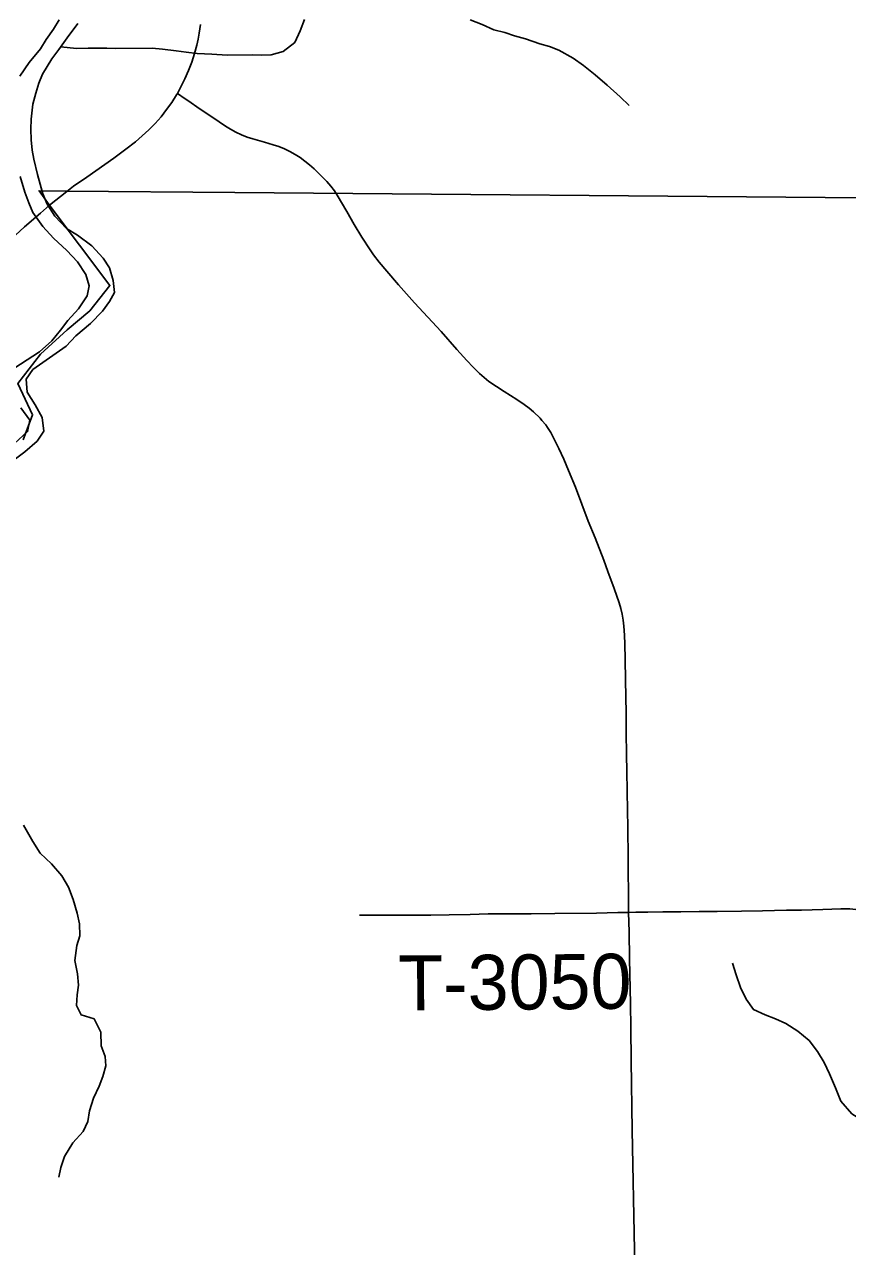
# Model space of a CAD drawing. Extents: x -7.5 to 53.5, y 0 to 22.
# Drawn here: x 3.721 to 4.57, y 15.27 to 16.532 of the extents above; entities that cross this region are included whole.
import ezdxf

# ---------------------------------------------------------------- set-up
doc = ezdxf.new("R2010")
doc.units = 0
for name, color, linetype in [('GM_X_Corporation', 7, 'Continuous'), ('GM_X_County_Road', 7, 'Continuous'), ('GM_X_Major_River', 7, 'Continuous'), ('GM_X_Minor_River', 7, 'Continuous'), ('GM_X_State_Route', 7, 'Continuous'), ('GM_X_Township_Road', 7, 'Continuous'), ('GM_X_Township_Road_Text', 7, 'Continuous')]:
    doc.layers.add(name, color=color, linetype=linetype)

msp = doc.modelspace()

# ---------------------------------------------------------------- linework, layer by layer
at = {"layer": 'GM_X_Corporation'}
msp.add_lwpolyline([(4.5873, 16.3533), (3.9378, 16.3588), (3.7641, 16.3602), (3.7357, 16.3606), (3.7462, 16.3461), (3.8088, 16.2627), (3.788, 16.2365), (3.7647, 16.2168), (3.737, 16.1919), (3.7138, 16.1615), (3.729, 16.1293), (3.7192, 16.1034)], dxfattribs=at)
at = {"layer": 'GM_X_County_Road'}
for points in [[(4.0432, 16.3561), (4.0404, 16.3605), (4.0367, 16.3654), (4.0326, 16.37), (4.0262, 16.3767), (4.0195, 16.3831), (4.0148, 16.3872), (4.01, 16.3911), (4.005, 16.3947), (3.9998, 16.398), (3.9944, 16.4011), (3.9889, 16.4037), (3.9831, 16.4061), (3.9773, 16.4081), (3.9683, 16.4107), (3.9563, 16.414), (3.9503, 16.416), (3.9445, 16.4183), (3.9388, 16.4209), (3.9333, 16.424), (3.9279, 16.4273), (3.9149, 16.436), (3.902, 16.4448), (3.8891, 16.4536), (3.8865, 16.4554), (3.8784, 16.4611)], [(4.344, 15.6154), (4.3438, 15.6342), (4.3436, 15.6591), (4.3435, 15.6716), (4.343, 15.7027), (4.3428, 15.7214), (4.3426, 15.74), (4.3422, 15.7618), (4.3419, 15.7773), (4.3416, 15.8022), (4.3415, 15.8209), (4.3409, 15.8551), (4.3405, 15.8769), (4.3402, 15.8924), (4.3398, 15.9017), (4.339, 15.911), (4.3382, 15.9171), (4.3372, 15.9232), (4.3358, 15.9292), (4.3341, 15.9351), (4.329, 15.9497), (4.3227, 15.9673), (4.3183, 15.979), (4.3093, 16.0022), (4.3024, 16.0195), (4.2957, 16.0369), (4.289, 16.0544), (4.2821, 16.0717), (4.2772, 16.0832), (4.2721, 16.0944), (4.2666, 16.1055), (4.2636, 16.1109), (4.2603, 16.1161), (4.2585, 16.1187), (4.2546, 16.1234), (4.2526, 16.1257), (4.2459, 16.1321), (4.2412, 16.1361), (4.2363, 16.1398), (4.2286, 16.145), (4.2154, 16.1532), (4.2075, 16.1583), (4.1998, 16.1637), (4.1949, 16.1676), (4.1902, 16.1718), (4.1835, 16.1784), (4.1772, 16.1852), (4.1668, 16.1967), (4.1504, 16.2153), (4.1232, 16.2449), (4.1067, 16.2634), (4.0945, 16.2774), (4.0865, 16.2869), (4.0808, 16.2943), (4.0772, 16.2994), (4.0688, 16.3125), (4.0609, 16.3258), (4.0532, 16.3392), (4.0432, 16.3561)], [(4.3617, 15.1179), (4.356, 15.1334), (4.3539, 15.1425), (4.3524, 15.1517), (4.3516, 15.161), (4.3512, 15.1766), (4.3511, 15.2169), (4.3502, 15.2665), (4.3475, 15.3906), (4.3465, 15.462), (4.3463, 15.4961), (4.346, 15.5209), (4.345, 15.5673), (4.3444, 15.5952), (4.344, 15.6154)]]:
    msp.add_lwpolyline(points, dxfattribs=at)
at = {"layer": 'GM_X_Major_River'}
for points in [[(3.7565, 16.5369), (3.7505, 16.5274), (3.743, 16.5167), (3.737, 16.5072), (3.7253, 16.4931), (3.7159, 16.4787)], [(3.7636, 16.1999), (3.7735, 16.2106), (3.7886, 16.2236), (3.801, 16.2361), (3.8085, 16.246), (3.8134, 16.2555), (3.8122, 16.268), (3.8084, 16.2809), (3.8019, 16.2908), (3.7901, 16.3036), (3.7753, 16.3146), (3.7639, 16.3214), (3.7521, 16.3342), (3.7441, 16.3467), (3.7395, 16.3573), (3.7368, 16.3672), (3.7341, 16.3774), (3.7302, 16.393), (3.7287, 16.4024), (3.7275, 16.4131), (3.7271, 16.4241), (3.7274, 16.4343), (3.7292, 16.4499), (3.7322, 16.4613), (3.7356, 16.4715), (3.7393, 16.481), (3.7487, 16.4966), (3.7559, 16.5065), (3.7646, 16.5183), (3.7755, 16.5332)], [(3.7163, 16.3751), (3.7209, 16.3592), (3.7251, 16.3482), (3.7293, 16.3379), (3.7396, 16.3236), (3.7507, 16.3115), (3.7644, 16.299), (3.7754, 16.2873), (3.7838, 16.274), (3.7873, 16.2623), (3.7854, 16.252), (3.7764, 16.2387), (3.7654, 16.2265), (3.7579, 16.2166), (3.7488, 16.2056), (3.736, 16.1941)], [(3.736, 16.1941), (3.7039, 16.1731)], [(3.7085, 16.0817), (3.7209, 16.0909), (3.7337, 16.102), (3.7405, 16.1123), (3.7388, 16.1264), (3.7315, 16.1396), (3.7234, 16.1524), (3.7222, 16.1661), (3.7293, 16.176), (3.7636, 16.1999)], [(3.7167, 16.1364), (3.7263, 16.1236), (3.7238, 16.1118), (3.7102, 16.0995)]]:
    msp.add_lwpolyline(points, dxfattribs=at)
at = {"layer": 'GM_X_Minor_River'}
for points in [[(3.7578, 16.5091), (3.7745, 16.5074), (3.7862, 16.5078), (3.8055, 16.5079), (3.815, 16.5075), (3.8522, 16.5077), (3.8632, 16.5069), (3.8772, 16.5051), (3.8874, 16.5036), (3.8988, 16.5021), (3.914, 16.5014), (3.9299, 16.5007), (3.9556, 16.5008), (3.9655, 16.5005), (3.9753, 16.5009), (3.9875, 16.5044), (3.9995, 16.5135), (4.0052, 16.5257), (4.0097, 16.5375)], [(4.1806, 16.537), (4.1927, 16.5321), (4.2049, 16.5268), (4.2163, 16.5238), (4.2261, 16.5205), (4.2375, 16.5175), (4.2523, 16.5122), (4.2622, 16.5096), (4.2721, 16.5058), (4.2869, 16.4975), (4.2975, 16.49), (4.3093, 16.4802), (4.3219, 16.4696), (4.3352, 16.4575), (4.3447, 16.4484)], [(3.7195, 15.7054), (3.7291, 15.6884), (3.7368, 15.6764), (3.7486, 15.6655), (3.759, 15.653), (3.7659, 15.6413), (3.771, 15.6285), (3.7749, 15.6145), (3.7773, 15.6035), (3.7778, 15.591), (3.7748, 15.5811), (3.7727, 15.5655), (3.7754, 15.5519), (3.7763, 15.5401), (3.7749, 15.5303), (3.7742, 15.5192), (3.7792, 15.5094), (3.7925, 15.5054), (3.7995, 15.4918), (3.7996, 15.4777), (3.8039, 15.4664), (3.8047, 15.4569), (3.8014, 15.4459), (3.7977, 15.436), (3.7918, 15.4234), (3.7877, 15.4105), (3.7859, 15.3995), (3.7811, 15.3892), (3.7706, 15.3773), (3.762, 15.3632), (3.7583, 15.3518), (3.7561, 15.3419)], [(4.5998, 15.3899), (4.5998, 15.3918), (4.5861, 15.4), (4.5742, 15.4075), (4.5631, 15.4203), (4.5573, 15.4343), (4.5511, 15.4486), (4.5457, 15.4603), (4.5388, 15.4717), (4.5303, 15.483), (4.5185, 15.4927), (4.5063, 15.5006), (4.4956, 15.5054), (4.485, 15.5095), (4.4728, 15.5151), (4.4651, 15.5256), (4.4593, 15.5377), (4.455, 15.5509), (4.4511, 15.563)]]:
    msp.add_lwpolyline(points, dxfattribs=at)
at = {"layer": 'GM_X_State_Route'}
msp.add_line((3.7464, 16.3455), (3.7643, 16.3596), dxfattribs=at)
for points in [[(3.7643, 16.3596), (3.7713, 16.3651), (3.7849, 16.3745), (3.8128, 16.3941), (3.8253, 16.4034), (3.835, 16.411), (3.8421, 16.4171), (3.8489, 16.4234), (3.8554, 16.4301), (3.8615, 16.437), (3.8673, 16.4443), (3.8726, 16.4518), (3.8776, 16.4597), (3.8784, 16.4611), (3.8821, 16.4678), (3.8862, 16.4761), (3.8899, 16.4846), (3.8933, 16.4933), (3.8962, 16.5021), (3.8986, 16.511), (3.8999, 16.517), (3.9009, 16.5231), (3.9021, 16.5323)], [(3.61, 16.2106), (3.633, 16.2349), (3.6447, 16.247), (3.6761, 16.2798), (3.6936, 16.2975), (3.707, 16.3105), (3.7208, 16.3231), (3.7371, 16.3375), (3.7464, 16.3455)]]:
    msp.add_lwpolyline(points, dxfattribs=at)
at = {"layer": 'GM_X_Township_Road'}
for points in [[(4.0664, 15.6126), (4.1058, 15.6125), (4.14, 15.6126), (4.1587, 15.6127), (4.1805, 15.6131), (4.1992, 15.6137), (4.2116, 15.6139), (4.2434, 15.6139), (4.268, 15.6142), (4.311, 15.6146), (4.3328, 15.6151), (4.344, 15.6154)], [(4.344, 15.6154), (4.3515, 15.6155), (4.3639, 15.6157), (4.3794, 15.6158), (4.398, 15.616), (4.4167, 15.6162), (4.4354, 15.6164), (4.4603, 15.6166), (4.4821, 15.6168), (4.5069, 15.6175), (4.5225, 15.6178), (4.5442, 15.6185), (4.5629, 15.6191), (4.5722, 15.6189), (4.5815, 15.6181), (4.5887, 15.6171), (4.5954, 15.6155), (4.6023, 15.6133)]]:
    msp.add_lwpolyline(points, dxfattribs=at)

# ---------------------------------------------------------------- texts
at = {"layer": 'GM_X_Township_Road_Text'}
msp.add_text('T-3050', height=0.05682, rotation=0.4648, dxfattribs=at).set_placement((4.1064, 15.514))

doc.saveas('drawing.dxf')
